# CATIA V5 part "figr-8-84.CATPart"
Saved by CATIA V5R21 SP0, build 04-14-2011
Part number: Part1
Bounding box of the stored display mesh (mm): x -44.701 to 35.128, y -35.23 to 15.392, z -47.191 to 31.322
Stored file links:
  D:\CATIA V5R21 E-RESOURCES\CATIA-V5R21\catia-v5r21-prt\c08-catia-v5r20-prt\c08-catia-v5r21-figr-8-84.CATPart
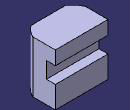
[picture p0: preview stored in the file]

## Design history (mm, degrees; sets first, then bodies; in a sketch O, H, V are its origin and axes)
Body1 (main body)
  Sketch1 on xy-plane, origin (0, 0, 0), H (1, 0, 0), V (0, 1, 0)
    line L1 (-44.7013, 25.8759) -> (35.1284, 25.8759)
    line L2 (35.1284, 25.8759) -> (35.1284, -18.9612)
    line L3 (-44.7013, 25.8759) -> (-44.7013, -18.9612)
    arc A1 centre (-4.7865, 1.0752) radius 44.6615 from (-44.7013, -18.9612) to (35.1284, -18.9612) ccw
    horizontal: L1 H
    vertical: L2 V, L3 V
  Sketch2 on yz-plane, origin (0, 0, 0), H (0, 1, 0), V (0, 0, 1)
    line L1 (-35.2302, 31.3221) -> (-35.2302, -47.1914)
    point P2 (-35.2302, -47.1914)
    point P3 (-35.2302, -47.1914)
    line L2 (-35.2302, -47.1914) -> (15.3919, -47.1914)
    point P4 (15.3919, -47.1914)
    line L3 (15.3919, 31.3221) -> (-35.2302, 31.3221)
    line L4 (15.3919, 31.3221) -> (15.3919, 10.6589)
    line L5 (15.3919, 10.6589) -> (1.7321, 10.6589)
    line L6 (1.7321, 10.6589) -> (1.7321, -13.9018)
    line L7 (1.7321, -13.9018) -> (15.3919, -13.9018)
    point P9 (15.3919, -13.9018)
    line L8 (15.3919, -13.9018) -> (15.3919, -47.1914)
    point P10 (15.3919, -47.1914)
    vertical: L1 V, L4 V, L6 V, L8 V
    horizontal: L2 H, L3 H, L5 H, L7 H
    coincidence: P9 L4, P10 L2, P10 P4, P3 P2
  SolidCombine1: FirstComponentDirection Sketch1, FirstComponentProfile Sketch1, SecondComponentDirection Sketch2, SecondComponentProfile Sketch2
